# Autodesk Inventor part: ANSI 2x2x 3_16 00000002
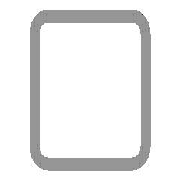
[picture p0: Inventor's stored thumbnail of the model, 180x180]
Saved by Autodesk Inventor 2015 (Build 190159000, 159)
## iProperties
IsCustomPart: 1
Created: 2007-02
Part Number: ANSI 2x2x 3_16 00000002
Material: Steel
Document SubType Name: Modeling
Standard: AISC
Designer: Autodesk, Inc.
Size Designation: 2x2x3/16
Stock Number: 2x2x 3/16
Density: 7.85 g/cm^3
Description: Tube
Standards Organization: ANSI
Language: en-US
Categories: <MemberInstance><Categories><Category DisplayName="Structural Shapes" InternalName="089c4875-fa83-4c05-b084-43b9cc11f5ed" Mnemonic="GRDR"><CategoryParameter Dis
Mass: 3346.04 g
Surface Area: 1806.39 cm^2
Volume: 426.248 cm^3
Appearance: Steel
_FrameMemberDoc: Frame Member File
_Version: 15.0.0
_CCFamilyMember: 1
_CCFamilyDisplayName: ANSI AISC (Square) - Tube
G_L: 20.500 in
G_W: 2.000 in
G_H: 2.000 in
+BE703474-FAC7-4A76-A1B7-63681628EF96+CUTDETAIL1: Cut
+DAD38F74-55C7-49BC-9A84-6C9A1DEB4C8E+CUTDETAIL2: Cut
Author: Autodesk, Inc.
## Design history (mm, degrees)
node "Start plane"
node "End plane"
sketch "Sketch"
  geometry: L1 (-25.4, -15.875)-(-25.4, 15.875); L2 (-15.875, 25.4)-(15.875, 25.4); L3 (25.4, 15.875)-(25.4, -15.875); L4 (15.875, -25.4)-(-15.875, -25.4); L5 (-15.875, 20.637)-(15.875, 20.638); L6 (20.637, 15.875)-(20.637, -15.875); L7 (15.875, -20.637)-(-15.875, -20.638); L8 (-20.637, -15.875)-(-20.637, 15.875); L9 (0, 38.322)-(0, -38.322) reference; L10 (-38.322, 0)-(38.322, 0) reference; A1 r 9.525 centre (-15.875, -15.875) between (-25.4, -15.875) and (-15.875, -25.4); A2 r 9.525 centre (-15.875, 15.875) between (-15.875, 25.4) and (-25.4, 15.875); A3 r 9.525 centre (15.875, 15.875) between (25.4, 15.875) and (15.875, 25.4); A4 r 9.525 centre (15.875, -15.875) between (15.875, -25.4) and (25.4, -15.875); A5 r 4.762 centre (-15.875, 15.875) between (-15.875, 20.637) and (-20.637, 15.875); A6 r 4.762 centre (15.875, 15.875) between (20.637, 15.875) and (15.875, 20.638); A7 r 4.762 centre (15.875, -15.875) between (15.875, -20.637) and (20.637, -15.875); A8 r 4.762 centre (-15.875, -15.875) between (-20.637, -15.875) and (-15.875, -20.638)
  constraints: 16 end point, 16 point on circle, 8 centre point, 8 tangent, 4 parallel, 3 equal radius, 2 perpendicular, 7 other
  dimensions: "d10" = 50.8 distance between parallel lines of L2 L4 (= G_H); "d11" = 50.8 distance between parallel lines of L1 L3 (= G_W); "d12" = 4.7625 distance between parallel lines of L3 L6 (= G_T); "d15" = 25.4 distance between parallel lines of L2 L10 (= 0.5 x d10); "d16" = 25.4 distance between parallel lines of L9 L3 (= 0.5 x d11); "d17" = 9.525 radius of A1 (= G_IR)
extrude "Body" new body sketch "Sketch" stored distance "d3" = 520.7 (= G_L); taper "d4" = 0 deg
node "Driven Length"
  sketch "Sketch4"
    geometry: L1 (0, 0)-(10, 0) reference
    constraints: 2 end point, 1 horizontal
  workplane "Work Plane5"
  sketch "Sketch5"
    geometry: L1 (-2, -6.35)-(12, -6.35) reference; L2 (-2, 514.35)-(12, 514.35) reference
    dimensions: "d26" = 520.7 distance between parallel lines of L1 L2 (derived)
workplane "Work Plane3"
split "Split1"
workplane "Work Plane4"
split "Split2"
body "Solid1"
other parameters: "G_W" = 50.8 [user parameter; used in 1 equation term], "G_H" = 50.8 [user parameter; used in 1 equation term], "G_T" = 4.7625 [user parameter; used in 1 equation term], "G_IR" = 9.525 [user parameter; used in 1 equation term], "G_L" = 520.7 (= d26) [user parameter; used in 1 equation term], "G_OFFSET_START" = 6.35 [user parameter; used in 1 equation term], "G_OFFSET_END" = 6.35 [user parameter; used in 1 equation term], "d13" = -6.35 (= -G_OFFSET_START), "d14" = 514.35 (= G_OFFSET_END + B_L), "B_L" = 508 [user parameter; used in 1 equation term], "d25" = 90 deg
